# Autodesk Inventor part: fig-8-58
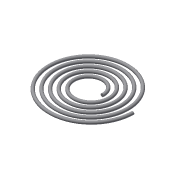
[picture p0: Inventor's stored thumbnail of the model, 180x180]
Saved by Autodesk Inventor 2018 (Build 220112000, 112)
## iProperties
Shininess: 77.0
Length Units: 11269
Angle Units: 11279
Time Units: 11290
Mass Units: 11283
Length Display Precision: 3
Angle Display Precision: 2
Created: 2002-01
Part Number: fig-8-58
Document SubType Name: Modeling
Designer: CADSoft
Density: 1 g/cm^3
Material: Generic
Appearance: Default
Density: 0.0
Volumn: 0.0
Area: 0.0
PropertySet Name: Model Information
Control State: 0
Master: False
Checked Out: False
Author: CADSoft
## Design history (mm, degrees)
sketch "Sketch2"
  geometry: C1 r 2.5 at (-19.895, -0.092)
  constraints: 1 centre point
  dimensions: "d0" = 5 diameter of C1
coil "Coil5" sketch "Sketch2" pitch "d35" = 10; turns "d37" = 5; dims "d36" = 10, "d38" = 0, angle "d39" = 90 deg, angle "d40" = 90 deg, "d41" = 0, "d42" = 0
body "Solid1"
